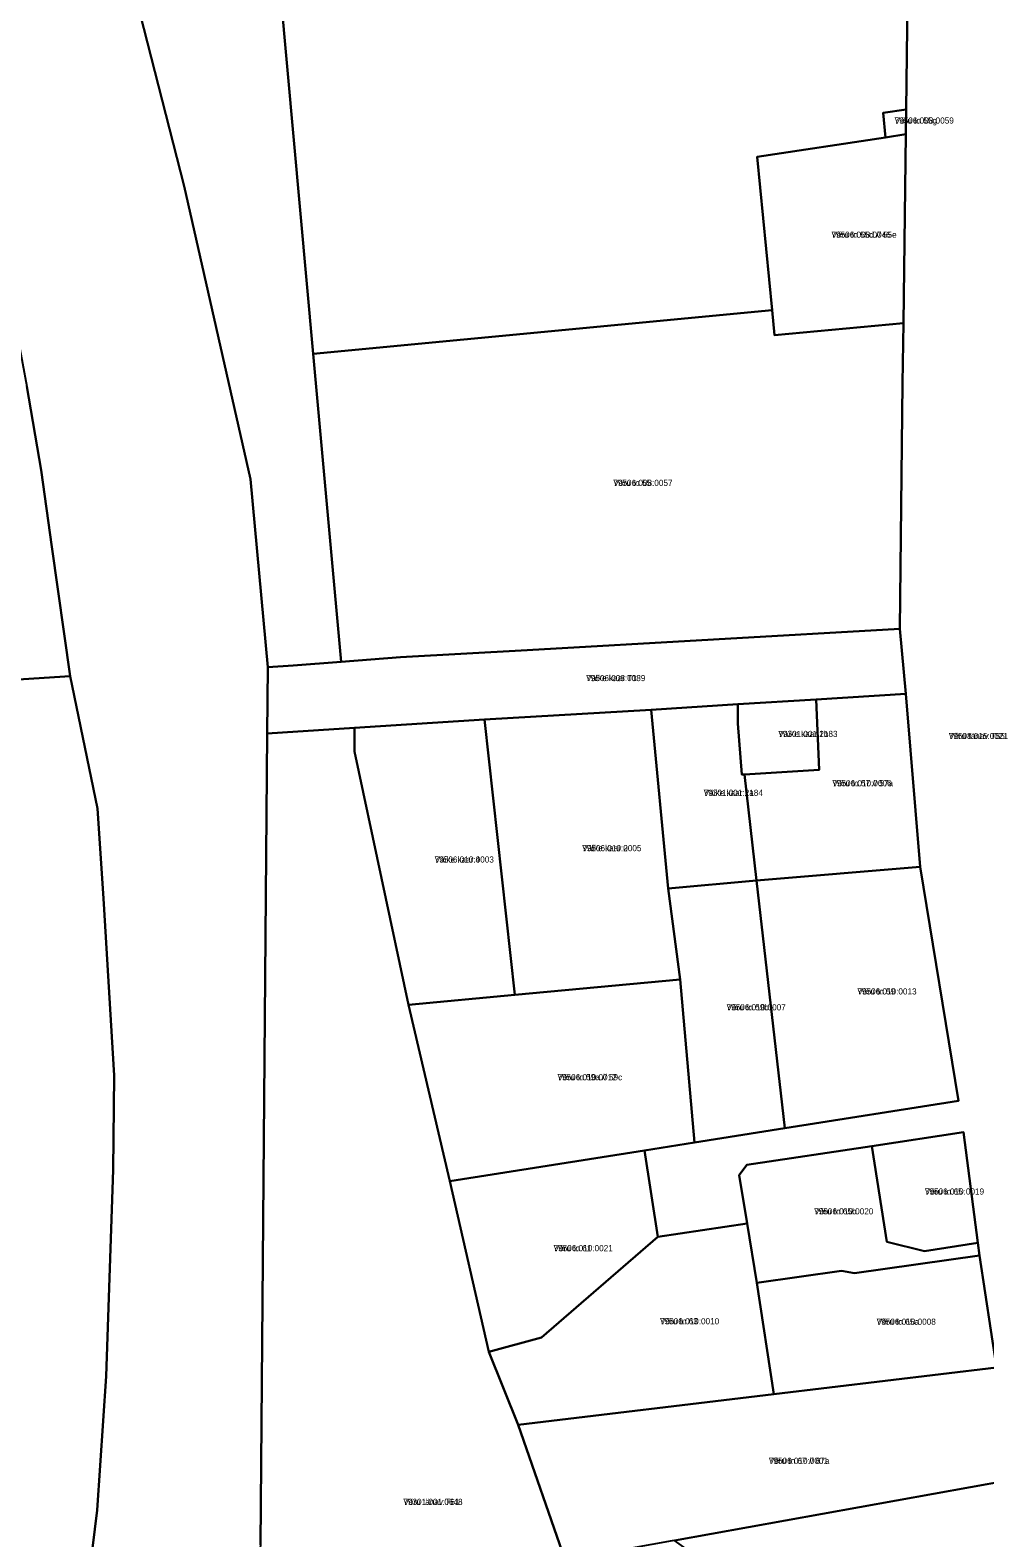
# Model space of a CAD drawing. Extents: x 643847 to 663718, y 6468443 to 6482775.
# Drawn here: x 658986.5 to 659220.2, y 6472257.2 to 6472626.3 of the extents above; entities that cross this region are included whole.
import ezdxf

# ---------------------------------------------------------------- set-up
doc = ezdxf.new("R2010")
doc.units = 0
for name, color, linetype in [('L_AADRESS', 7, 'Continuous'), ('PIIR', 7, 'Continuous'), ('TUNNUS', 7, 'Continuous')]:
    doc.layers.add(name, color=color, linetype=linetype)

msp = doc.modelspace()

# ---------------------------------------------------------------- linework, layer by layer
at = {"layer": 'PIIR'}
for points in [[(658995.57, 6472865.47), (659014.95, 6472824.56), (659022.75, 6472804.22), (659040.78, 6472757.22), (659037.43, 6472749.27), (659039.82, 6472722.99), (659055.78, 6472547.05), (659062.61, 6472471.69), (659050.89, 6472470.77), (659044.66, 6472470.33), (659040.43, 6472516.35), (659024.2, 6472588.11), (659010.67, 6472640.85), (658991.51, 6472707.96), (658967.36, 6472792.7), (658945.08, 6472841.12)], [(658967.36, 6472792.7), (658991.51, 6472707.96), (659010.67, 6472640.85), (659024.2, 6472588.11), (659040.43, 6472516.35), (659044.66, 6472470.33), (659044.52, 6472454.14), (659042.83, 6472255.53), (659037.46, 6472203.54), (659035.38, 6472167.52), (659035.13, 6472163.22), (659033.46, 6472141.48), (659008.24, 6472060.73), (658964.24, 6472065.35)], [(659229.09, 6472243.12), (659225.8, 6472271.29), (659223.06, 6472298.97), (659218.9, 6472326.37), (659218.51, 6472329.43), (659215, 6472356.51), (659192.6, 6472353.15), (659161.99, 6472348.57), (659160.1, 6472345.98), (659162.04, 6472334.15), (659140.17, 6472330.91), (659136.86, 6472352.07), (659149.1, 6472354), (659171.26, 6472357.49), (659213.75, 6472364.19), (659204.41, 6472421.46), (659200.88, 6472463.86), (659199.4, 6472479.76), (659200.1, 6472539.86), (659200.28, 6472554.61), (659200.87, 6472600.83), (659200.94, 6472606.9), (659201.61, 6472660.35)], [(658984.39, 6472140.38), (658990.16, 6472169.38), (658998.78, 6472230.84), (659002.89, 6472263.99), (659005.06, 6472296.8), (659006.83, 6472347.3), (659007, 6472370.43), (659004.44, 6472413.76), (659002.99, 6472435.79), (658996.26, 6472468.2), (658991.81, 6472499.86), (658989.18, 6472518.57), (658985.69, 6472539.06)], [(658967, 6472466.25), (658996.26, 6472468.2), (659002.99, 6472435.79), (659004.44, 6472413.76), (659007, 6472370.43), (659006.83, 6472347.3), (659005.06, 6472296.8), (659002.89, 6472263.99), (658998.78, 6472230.84), (658990.16, 6472169.38), (658984.39, 6472140.38)], [(659042.83, 6472255.53), (659044.52, 6472454.14), (659048.27, 6472454.39), (659065.85, 6472455.52), (659065.85, 6472449.73), (659079.07, 6472387.7), (659089.23, 6472344.57), (659098.76, 6472302.74), (659105.95, 6472284.9), (659117.5, 6472251.75)]]:
    msp.add_lwpolyline(points, dxfattribs=at)
for points in [[(659201.61, 6472660.35), (659200.94, 6472606.9), (659195.35, 6472606.03), (659195.93, 6472600.05), (659164.49, 6472595.28), (659168.12, 6472557.78), (659055.78, 6472547.05), (659039.82, 6472722.99), (659067.95, 6472725.71), (659075.52, 6472720.92), (659094.37, 6472722.74), (659137.82, 6472723.41), (659139.64, 6472705.8), (659167.03, 6472708.36), (659171.3, 6472659.85)], [(659200.94, 6472606.9), (659200.87, 6472600.83), (659195.93, 6472600.05), (659195.35, 6472606.03)], [(658944.62, 6472595.1), (658972.27, 6472603.53), (658977.12, 6472582.26), (658981.4, 6472561.91), (658985.69, 6472539.06), (658989.18, 6472518.57), (658991.81, 6472499.86), (658996.26, 6472468.2), (658967, 6472466.25), (658963.03, 6472501.5), (658957.44, 6472532.95), (658951.16, 6472563.93)], [(659200.87, 6472600.83), (659200.28, 6472554.61), (659168.72, 6472551.61), (659168.12, 6472557.78), (659164.49, 6472595.28), (659195.93, 6472600.05)], [(659200.28, 6472554.61), (659200.1, 6472539.86), (659199.4, 6472479.76), (659108.14, 6472474.57), (659077.18, 6472472.82), (659062.61, 6472471.69), (659055.78, 6472547.05), (659168.12, 6472557.78), (659168.72, 6472551.61)], [(659108.14, 6472474.57), (659199.4, 6472479.76), (659200.88, 6472463.86), (659178.91, 6472462.47), (659159.78, 6472461.3), (659138.5, 6472459.91), (659097.7, 6472457.55), (659065.85, 6472455.52), (659048.27, 6472454.39), (659044.52, 6472454.14), (659044.66, 6472470.33), (659050.89, 6472470.77), (659062.61, 6472471.69), (659077.18, 6472472.82)], [(659178.91, 6472462.47), (659200.88, 6472463.86), (659204.41, 6472421.46), (659164.29, 6472418.18), (659161.37, 6472444.1), (659179.68, 6472445.26)], [(659105.17, 6472390.17), (659097.7, 6472457.55), (659138.5, 6472459.91), (659142.73, 6472416.18), (659145.6, 6472393.92)], [(659138.5, 6472459.91), (659159.78, 6472461.3), (659159.73, 6472456.54), (659160.76, 6472444.09), (659161.37, 6472444.1), (659164.29, 6472418.18), (659142.73, 6472416.18)], [(659159.78, 6472461.3), (659178.91, 6472462.47), (659179.68, 6472445.26), (659161.37, 6472444.1), (659160.76, 6472444.09), (659159.73, 6472456.54)], [(659065.85, 6472449.73), (659065.85, 6472455.52), (659097.7, 6472457.55), (659105.17, 6472390.17), (659079.07, 6472387.7)], [(659213.75, 6472364.19), (659171.26, 6472357.49), (659164.29, 6472418.18), (659204.41, 6472421.46)], [(659171.26, 6472357.49), (659149.1, 6472354), (659145.6, 6472393.92), (659142.73, 6472416.18), (659164.29, 6472418.18)], [(659136.86, 6472352.07), (659089.23, 6472344.57), (659079.07, 6472387.7), (659105.17, 6472390.17), (659145.6, 6472393.92), (659149.1, 6472354)], [(659192.6, 6472353.15), (659196.27, 6472329.67), (659205.46, 6472327.43), (659218.51, 6472329.43), (659218.9, 6472326.37), (659188.3, 6472322.05), (659185.17, 6472322.61), (659164.41, 6472319.7), (659162.04, 6472334.15), (659160.1, 6472345.98), (659161.99, 6472348.57)], [(659215, 6472356.51), (659218.51, 6472329.43), (659205.46, 6472327.43), (659196.27, 6472329.67), (659192.6, 6472353.15)], [(659136.86, 6472352.07), (659140.17, 6472330.91), (659111.69, 6472306.3), (659098.76, 6472302.74), (659089.23, 6472344.57)], [(659162.04, 6472334.15), (659164.41, 6472319.7), (659168.6, 6472292.42), (659105.95, 6472284.9), (659098.76, 6472302.74), (659111.69, 6472306.3), (659140.17, 6472330.91)], [(659223.06, 6472298.97), (659168.6, 6472292.42), (659164.41, 6472319.7), (659185.17, 6472322.61), (659188.3, 6472322.05), (659218.9, 6472326.37)], [(659225.8, 6472271.29), (659144.26, 6472256.59), (659143.64, 6472256.48), (659124.68, 6472253.05), (659117.5, 6472251.75), (659105.95, 6472284.9), (659168.6, 6472292.42), (659223.06, 6472298.97)], [(659229.09, 6472243.12), (659219.15, 6472242.09), (659165.95, 6472237.16), (659164.99, 6472241.74), (659144.26, 6472256.59), (659225.8, 6472271.29)]]:
    msp.add_lwpolyline(points, close=True, dxfattribs=at)

# ---------------------------------------------------------------- texts
at = {"layer": 'L_AADRESS'}
for s, p in [('Võru tn 55g', (659198.14, 6472603.43)), ('Võru tn 55d // 55e', (659182.68, 6472575.49)), ('Võru tn 55', (659129.26, 6472514.74)), ('Väike kaar T1', (659122.61, 6472466.95)), ('Väike kaar 2b', (659169.66, 6472453.28)), ('Võru tänav T55', (659211.4, 6472452.77)), ('Võru tn 57 // 57a', (659182.89, 6472441.21)), ('Väike kaar 2a', (659151.39, 6472438.87)), ('Väike kaar 2', (659121.65, 6472425.32)), ('Väike kaar 4', (659085.51, 6472422.54)), ('Võru tn 59', (659189.02, 6472390.25)), ('Võru tn 59b', (659156.99, 6472386.37)), ('Võru tn 59a // 59c', (659115.59, 6472369.25)), ('Võru tn 65', (659205.55, 6472341.27)), ('Võru tn 65b', (659178.44, 6472336.42)), ('Võru tn 61', (659114.63, 6472327.4)), ('Võru tn 63', (659140.7, 6472309.52)), ('Võru tn 65a', (659193.73, 6472309.4)), ('Võru tn 67 // 67a', (659167.34, 6472275.36)), ('Võru tänav T61', (659077.85, 6472265.3))]:
    msp.add_text(s, height=1.5, dxfattribs=at).set_placement(p)
at = {"layer": 'TUNNUS'}
for s, p in [('79506:008:0059', (659198.14, 6472603.43)), ('79506:008:0046', (659182.68, 6472575.49)), ('79506:008:0057', (659129.26, 6472514.74)), ('79506:008:0089', (659122.61, 6472466.95)), ('79301:001:1183', (659169.66, 6472453.28)), ('79508:015:0021', (659211.4, 6472452.77)), ('79506:010:0006', (659182.89, 6472441.21)), ('79301:001:1184', (659151.39, 6472438.87)), ('79506:010:0005', (659121.65, 6472425.32)), ('79506:010:0003', (659085.51, 6472422.54)), ('79506:010:0013', (659189.02, 6472390.25)), ('79506:010:0007', (659156.99, 6472386.37)), ('79506:010:0012', (659115.59, 6472369.25)), ('79506:010:0019', (659205.55, 6472341.27)), ('79506:010:0020', (659178.44, 6472336.42)), ('79506:010:0021', (659114.63, 6472327.4)), ('79506:010:0010', (659140.7, 6472309.52)), ('79506:010:0008', (659193.73, 6472309.4)), ('79506:010:0001', (659167.34, 6472275.36)), ('79301:001:0648', (659077.85, 6472265.3))]:
    msp.add_text(s, height=1.5, dxfattribs=at).set_placement(p)

doc.saveas('drawing.dxf')
